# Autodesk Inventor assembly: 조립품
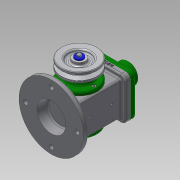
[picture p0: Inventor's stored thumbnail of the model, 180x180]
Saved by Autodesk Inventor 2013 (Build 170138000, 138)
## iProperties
Created: 2018-10
Part Number: 조립품
Document SubType Name: Assembly
Designer: Administrator
Author: Administrator
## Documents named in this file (18)
- C:\Users\Administrator\Desktop\481007V1056\481007V1056\조립품.iam
- C:\Users\Administrator\Desktop\481007V1056\481007V1056\E-링.ipt
- C:\Users\Administrator\Desktop\481007V1056\481007V1056\V-벨트풀리.ipt
- C:\Users\Administrator\Desktop\481007V1056\481007V1056\덮개.ipt
- C:\Users\Administrator\Desktop\481007V1056\481007V1056\뒤커버.ipt
- C:\Users\Administrator\Desktop\481007V1056\481007V1056\링크.ipt
- C:\Users\Administrator\Desktop\481007V1056\481007V1056\베어링 17 x 40 x 12.ipt
- C:\Users\Administrator\Desktop\481007V1056\481007V1056\본체.ipt
- C:\Users\Administrator\Desktop\481007V1056\481007V1056\볼트 M4 x 8.ipt
- C:\Users\Administrator\Desktop\481007V1056\481007V1056\볼트 M4 x 10.ipt
- C:\Users\Administrator\Desktop\481007V1056\481007V1056\슬라이더.ipt
- C:\Users\Administrator\Desktop\481007V1056\481007V1056\앞커버.ipt
- C:\Users\Administrator\Desktop\481007V1056\481007V1056\오일 실 17 30 8.ipt
- C:\Users\Administrator\Desktop\481007V1056\481007V1056\와셔 4x16.ipt
- C:\Users\Administrator\Desktop\481007V1056\481007V1056\클레비스 핀 6 x 22.ipt
- 클레비스 핀 6 x 22.ipt
- C:\Users\Administrator\Desktop\481007V1056\481007V1056\키 4 x 4 x 12.ipt
- C:\Users\Administrator\Desktop\481007V1056\481007V1056\편심축.ipt
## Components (2 placed, 2 different names)
1. E-링:1
2. V-벨트풀리:1
